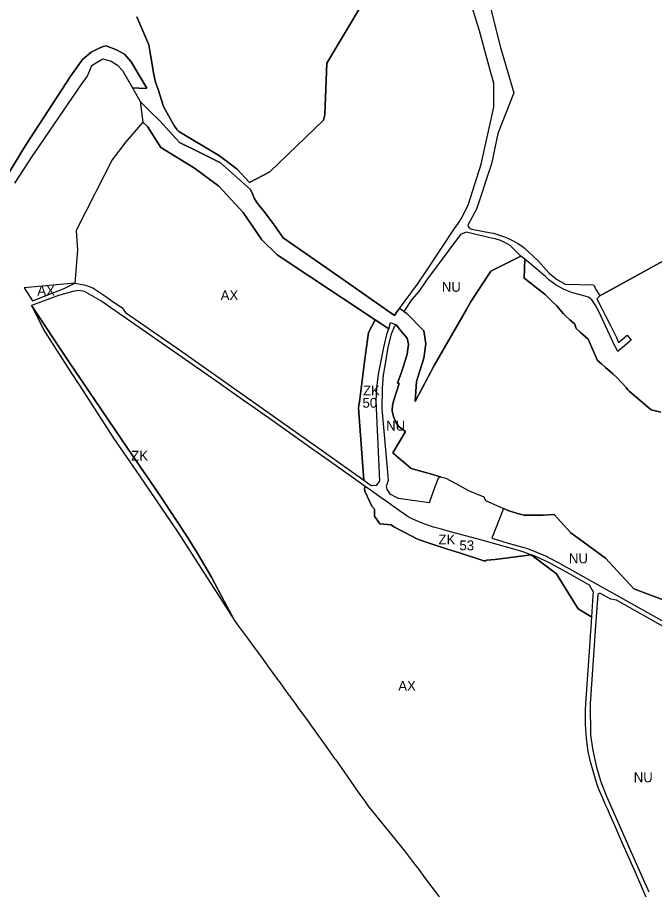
# Model space of a CAD drawing. Extents: x -521939 to -516426, y -1197857 to -1189551.
# Drawn here: x -519377 to -518730, y -1194658 to -1193772 of the extents above; entities that cross this region are included whole.
import ezdxf

# ---------------------------------------------------------------- set-up
doc = ezdxf.new("R2010")
doc.units = 0
for name, color, linetype in [('90640013', 7, 'Continuous'), ('90710013', 7, 'Continuous'), ('90710023', 7, 'Continuous'), ('90730013', 7, 'Continuous'), ('90760013', 7, 'Continuous'), ('ID_navrh', 7, 'Continuous')]:
    doc.layers.add(name, color=color, linetype=linetype)

msp = doc.modelspace()

# ---------------------------------------------------------------- linework, layer by layer
at = {"layer": '90640013'}
for points in [[(-519260.59, -1193843.56), (-519254.04, -1193843.81), (-519247.48, -1193844.06), (-519246.03, -1193843.78), (-519261.79, -1193816.98), (-519268.67, -1193809.37), (-519276.88, -1193804.99), (-519287.39, -1193800.73), (-519290.34, -1193801.33), (-519294.27, -1193803.26), (-519302.54, -1193807.3), (-519311.2, -1193814.52), (-519323.09, -1193831.25), (-519369.32, -1193902.04), (-519392.44, -1193939.94)], [(-519380, -1193940.17), (-519361.83, -1193912.1), (-519359.6, -1193908.65), (-519312.51, -1193840.49), (-519306.7, -1193831.79), (-519305.86, -1193830.53), (-519301.72, -1193820.72), (-519297.22, -1193817.84), (-519290.56, -1193813.88), (-519282.04, -1193816.28), (-519275.8, -1193820.56), (-519270.58, -1193825.99), (-519260.59, -1193843.56)], [(-518723.34, -1194172.97), (-518733.26, -1194170.62), (-518755.73, -1194151.42), (-518756.87, -1194150.17), (-518758.5, -1194148.35), (-518768.19, -1194137.67), (-518772.3, -1194134.01), (-518779.55, -1194127.56), (-518783.83, -1194123.78), (-518787.71, -1194120.29), (-518790.2, -1194114.91), (-518797.22, -1194098.85), (-518805.32, -1194091.65), (-518809.4, -1194088.06), (-518810.87, -1194083.64), (-518815.94, -1194078.99), (-518820.23, -1194075.04), (-518822.48, -1194072.97), (-518827.78, -1194066.65), (-518829.19, -1194065.02), (-518833.88, -1194060.52), (-518841.13, -1194053.49), (-518842.7, -1194051.99), (-518848.33, -1194047.58), (-518856.71, -1194041.04), (-518862.24, -1194036.73), (-518861.8, -1194017.37), (-518865.76, -1194014.41), (-518896.14, -1194029.57), (-518916.93, -1194061.2), (-518921.14, -1194068.53), (-518953.95, -1194125.44), (-518973.19, -1194162.2), (-518971.79, -1194141.85), (-518968.52, -1194131.03), (-518964.36, -1194117.94), (-518962.32, -1194103.53), (-518964.52, -1194090.45), (-518981.72, -1194072.81), (-518984.64, -1194070.77), (-518989.19, -1194067.6), (-518991.71, -1194071.11), (-518994.22, -1194074.61), (-519050.8, -1194035.17), (-519107.38, -1193995.73), (-519116.99, -1193982.41), (-519126.59, -1193969.09), (-519130.42, -1193964.54), (-519134.25, -1193959.98), (-519136.7, -1193955.42), (-519138.63, -1193951.03), (-519140.56, -1193946.64), (-519155.83, -1193933.12), (-519171.1, -1193919.6), (-519191.98, -1193909.24), (-519212.86, -1193898.88), (-519222.82, -1193887.86), (-519232.78, -1193876.84), (-519242.8, -1193867.04), (-519252.82, -1193857.23), (-519249.93, -1193878.39), (-519245.14, -1193882.61), (-519231.57, -1193904.08), (-519197.38, -1193925.03), (-519172.57, -1193943.22), (-519147.85, -1193970.15), (-519129.07, -1193997.96), (-519113.44, -1194013.16), (-519013.71, -1194079.07), (-518999.95, -1194088.17), (-518998.31, -1194081.79), (-518992.34, -1194084.24)], [(-518992.34, -1194084.24), (-518987.46, -1194090.71), (-518981.15, -1194097.64), (-518979.93, -1194103.79), (-518981.36, -1194113.88), (-518985.48, -1194127.27), (-518987.54, -1194133.31), (-518990.75, -1194142.5), (-518991.04, -1194143.46), (-518989.57, -1194143.91), (-518994.89, -1194160.62), (-518996.22, -1194165.66), (-518996.46, -1194171.39), (-518995.35, -1194177.39), (-518992.7, -1194183.09), (-518989.97, -1194187.05), (-518987.24, -1194189.51), (-518983, -1194192.63), (-518995.91, -1194214.24), (-518988.08, -1194220.82), (-518984.22, -1194224), (-518977.21, -1194230.09), (-518968.6, -1194232.51), (-518962.5, -1194234.23), (-518957.42, -1194235.65), (-518947.28, -1194238.51), (-518942.14, -1194239.95), (-518937.68, -1194242.28), (-518931.93, -1194245.39), (-518922.65, -1194250.42), (-518918.24, -1194252.79), (-518916.45, -1194253.54), (-518912.68, -1194255.11), (-518903.43, -1194258.95), (-518901.77, -1194262.69), (-518884.06, -1194270.49), (-518883.22, -1194270.86), (-518877.97, -1194273.16), (-518871.17, -1194275.18), (-518869.07, -1194275.8), (-518867.56, -1194276.25), (-518862.81, -1194277.65), (-518855.61, -1194277.58), (-518843.09, -1194277.49), (-518831.78, -1194276.92), (-518814.85, -1194295.64), (-518779.83, -1194321.26), (-518750.93, -1194352.24), (-518718.32, -1194364.43)]]:
    msp.add_lwpolyline(points, dxfattribs=at)
at = {"layer": '90710013'}
msp.add_lwpolyline([(-519157.23, -1194383.9), (-519165.07, -1194369.2), (-519169.9, -1194359.97), (-519173.46, -1194353.25), (-519180.17, -1194340.54), (-519194.88, -1194315.71), (-519205.17, -1194298.93), (-519230.46, -1194260.8), (-519243.94, -1194240.87), (-519248.58, -1194234.02), (-519265.68, -1194209.52), (-519325.55, -1194120.93), (-519363.03, -1194064.67), (-519362.31, -1194066.11), (-519350.72, -1194089.46), (-519329.11, -1194123.6), (-519317.88, -1194140.81), (-519314.59, -1194145.01), (-519279.95, -1194199.35), (-519253.43, -1194237.74), (-519214.57, -1194294.83), (-519157.23, -1194383.9)], dxfattribs=at)
at = {"layer": '90710023'}
for points in [[(-519025.2, -1194242.02), (-519017.78, -1194247.27), (-519012.22, -1194247.18), (-519009.11, -1194242.54), (-519012.79, -1194161.44), (-519012.2, -1194148.13), (-519010.43, -1194134.4), (-519004.84, -1194105.44), (-519001.62, -1194092.79), (-518999.95, -1194088.17), (-519013.71, -1194079.07), (-519020.73, -1194091.88), (-519024.61, -1194121.8), (-519028.49, -1194151.72), (-519029.89, -1194162.52), (-519030.29, -1194165.62), (-519030.69, -1194168.71), (-519027.95, -1194205.37), (-519025.2, -1194242.02)], [(-518793.68, -1194380.64), (-518792.24, -1194359.26), (-518791.99, -1194355.76), (-518795.83, -1194348.62), (-518799.64, -1194346.49), (-518816.36, -1194337.16), (-518838.06, -1194325.4), (-518851.56, -1194319.21), (-518862.69, -1194315.05), (-518865.77, -1194314.1), (-518872.91, -1194311.92), (-518892.05, -1194306.64), (-518905.25, -1194303.03), (-518910.54, -1194301.58), (-518937.1, -1194294.31), (-518946.44, -1194291.75), (-518954.36, -1194289.64), (-518962.17, -1194287.03), (-518966.08, -1194285.71), (-518975.52, -1194281.45), (-518980.26, -1194279.31), (-518993.95, -1194269.72), (-519001.41, -1194264.41), (-519008.87, -1194259.09), (-519017.53, -1194252.96), (-519023.94, -1194248.41), (-519024.71, -1194250.04), (-519024.49, -1194253.08), (-519017.06, -1194268.42), (-519014.59, -1194271.5), (-519014.52, -1194278.4), (-519009.2, -1194286.28), (-518997.55, -1194287.28), (-518994.7, -1194289.4), (-518975.86, -1194299.17), (-518972.84, -1194300.73), (-518969.65, -1194302.39), (-518959.1, -1194305.82), (-518939.19, -1194312.3), (-518928.2, -1194315.87), (-518903.28, -1194323.98), (-518901.43, -1194323.75), (-518900.67, -1194323.31), (-518891.75, -1194322.51), (-518855.36, -1194317.86), (-518829.53, -1194336.97), (-518816.88, -1194357.57), (-518807.62, -1194372.64), (-518794.51, -1194380.48), (-518793.68, -1194380.64)]]:
    msp.add_lwpolyline(points, dxfattribs=at)
at = {"layer": '90730013'}
for points in [[(-519392.44, -1193939.94), (-519369.32, -1193902.04), (-519323.09, -1193831.25), (-519311.2, -1193814.52), (-519302.54, -1193807.3), (-519294.27, -1193803.26), (-519290.34, -1193801.33), (-519287.39, -1193800.73), (-519276.88, -1193804.99), (-519268.67, -1193809.37), (-519261.79, -1193816.98), (-519246.03, -1193843.78), (-519247.48, -1193844.06), (-519254.04, -1193843.81), (-519260.59, -1193843.56), (-519252.82, -1193857.23), (-519242.8, -1193867.04), (-519232.78, -1193876.84), (-519222.82, -1193887.86), (-519212.86, -1193898.88), (-519191.98, -1193909.24), (-519171.1, -1193919.6), (-519155.83, -1193933.12), (-519140.56, -1193946.64), (-519138.63, -1193951.03), (-519136.7, -1193955.42), (-519134.25, -1193959.98), (-519130.42, -1193964.54), (-519126.59, -1193969.09), (-519116.99, -1193982.41), (-519107.38, -1193995.73), (-519050.8, -1194035.17), (-518994.22, -1194074.61), (-518991.71, -1194071.11), (-518989.19, -1194067.6), (-518970.85, -1194043.01), (-518961.6, -1194029.39), (-518933.03, -1193986.3), (-518929.34, -1193981.24), (-518926.25, -1193976.62), (-518919.27, -1193962.65), (-518906.17, -1193921.14), (-518893.26, -1193863.08), (-518893.29, -1193838.77), (-518896.5, -1193826.92), (-518907.68, -1193785.6), (-518926.27, -1193725.26)], [(-518905.57, -1193725.38), (-518886.46, -1193802.5), (-518872.98, -1193848.37), (-518889.3, -1193889.95), (-518895.73, -1193920.57), (-518910.79, -1193966.72), (-518919.72, -1193983.02), (-518919.42, -1193984.21), (-518917.8, -1193986.11), (-518915.51, -1193987.1), (-518896.17, -1193990.58), (-518893.56, -1193991.17), (-518888.41, -1193992.64), (-518883.37, -1193994.4), (-518878.43, -1193996.47), (-518873.62, -1193998.81), (-518868.96, -1194001.44), (-518864.46, -1194004.33), (-518862.25, -1194005.95), (-518847.72, -1194019.68), (-518837.23, -1194031.38), (-518829.44, -1194037.71), (-518820.8, -1194042.81), (-518791.79, -1194043.69), (-518788.68, -1194049.26), (-518785.58, -1194054.84), (-518720.61, -1194019.07)], [(-519025.65, -1193756.19), (-519062.93, -1193818.34), (-519065.01, -1193870.53), (-519066.27, -1193876.16), (-519120.74, -1193928.89), (-519141.58, -1193939.77), (-519154.26, -1193925.95), (-519171.95, -1193912.59), (-519213.53, -1193887.89), (-519215.12, -1193886.12), (-519217.8, -1193882.51), (-519221.81, -1193875.3), (-519228.9, -1193862.43), (-519234.57, -1193845.15), (-519237, -1193837.71), (-519238.75, -1193829.99), (-519241.81, -1193812.07), (-519244.01, -1193799.73), (-519255.98, -1193771.28)], [(-518984.64, -1194070.77), (-518981.72, -1194072.81), (-518964.52, -1194090.45), (-518962.32, -1194103.53), (-518964.36, -1194117.94), (-518968.52, -1194131.03), (-518971.79, -1194141.85), (-518973.19, -1194162.2), (-518953.95, -1194125.44), (-518921.14, -1194068.53), (-518916.93, -1194061.2), (-518896.14, -1194029.57), (-518865.76, -1194014.41), (-518876.72, -1194003.63), (-518881.5, -1194000.92), (-518886.53, -1193998.68), (-518891.75, -1193996.93), (-518897.11, -1193995.69), (-518901.17, -1193994.65), (-518921.36, -1193990.1), (-518927.19, -1193992.35), (-518961.57, -1194038.67), (-518969.27, -1194050.28), (-518976.81, -1194058.82), (-518984.64, -1194070.77)], [(-518720.61, -1194019.07), (-518785.58, -1194054.84), (-518788.48, -1194057.64), (-518784.06, -1194066.31), (-518779.64, -1194074.99), (-518774.55, -1194084.96), (-518769.47, -1194094.94), (-518768.35, -1194097.15), (-518768.35, -1194097.16), (-518767.38, -1194099.7), (-518766.41, -1194102.26), (-518757.64, -1194094.78), (-518753.59, -1194099.63), (-518762.33, -1194107.13), (-518767.02, -1194111.44), (-518770.01, -1194106.27), (-518770.34, -1194105.7), (-518773.38, -1194099.24), (-518775.15, -1194094.55), (-518779.68, -1194085.15), (-518784.2, -1194075.75), (-518788.94, -1194065.87), (-518793.56, -1194058.95), (-518797.05, -1194056.07), (-518804.1, -1194053.89), (-518813.11, -1194051.65), (-518821.77, -1194048.27), (-518829.92, -1194043.82), (-518837.43, -1194038.35), (-518840.81, -1194035.16), (-518861.8, -1194017.37), (-518862.24, -1194036.73), (-518856.71, -1194041.04), (-518848.33, -1194047.58), (-518842.7, -1194051.99), (-518841.13, -1194053.49), (-518833.88, -1194060.52), (-518829.19, -1194065.02), (-518827.78, -1194066.65), (-518822.48, -1194072.97), (-518820.23, -1194075.04), (-518815.94, -1194078.99), (-518810.87, -1194083.64), (-518809.4, -1194088.06), (-518805.32, -1194091.65), (-518797.22, -1194098.85), (-518790.2, -1194114.91), (-518787.71, -1194120.29), (-518783.83, -1194123.78), (-518779.55, -1194127.56), (-518772.3, -1194134.01), (-518768.19, -1194137.67), (-518758.5, -1194148.35), (-518756.87, -1194150.17), (-518755.73, -1194151.42), (-518733.26, -1194170.62), (-518723.34, -1194172.97)], [(-518992.34, -1194084.24), (-518994.52, -1194086.35), (-518997.57, -1194093.58), (-519000.87, -1194106.75), (-519004.5, -1194128.01), (-519005.71, -1194135.09), (-519006.82, -1194148.88), (-519007.1, -1194169.38), (-519001.58, -1194230.24), (-519000.5, -1194242.27), (-519002.57, -1194248.44), (-519001.67, -1194251.84), (-518998.9, -1194255.97), (-518992.56, -1194259.17), (-518990.61, -1194260.15), (-518958.46, -1194264.63), (-518953.02, -1194249.57), (-518950.81, -1194243.44), (-518949.41, -1194239.58), (-518947.28, -1194238.51), (-518957.42, -1194235.65), (-518962.5, -1194234.23), (-518968.6, -1194232.51), (-518977.21, -1194230.09), (-518984.22, -1194224), (-518988.08, -1194220.82), (-518995.91, -1194214.24), (-518983, -1194192.63), (-518987.24, -1194189.51), (-518989.97, -1194187.05), (-518992.7, -1194183.09), (-518995.35, -1194177.39), (-518996.46, -1194171.39), (-518996.22, -1194165.66), (-518994.89, -1194160.62), (-518989.57, -1194143.91), (-518991.04, -1194143.46), (-518990.75, -1194142.5), (-518987.54, -1194133.31), (-518985.48, -1194127.27), (-518981.36, -1194113.88), (-518979.93, -1194103.79), (-518981.15, -1194097.64), (-518987.46, -1194090.71), (-518992.34, -1194084.24)], [(-518718.32, -1194364.43), (-518750.93, -1194352.24), (-518779.83, -1194321.26), (-518814.85, -1194295.64), (-518831.78, -1194276.92), (-518843.09, -1194277.49), (-518855.61, -1194277.58), (-518862.81, -1194277.65), (-518867.56, -1194276.25), (-518869.07, -1194275.8), (-518871.17, -1194275.18), (-518877.97, -1194273.16), (-518883.22, -1194270.86), (-518895.2, -1194301.05), (-518885.16, -1194303.95), (-518883.44, -1194304.45), (-518858.91, -1194311.54), (-518840.84, -1194318.92), (-518827.82, -1194325.64), (-518716.88, -1194387.49)], [(-518670.02, -1194641.47), (-518673.12, -1194633.99), (-518677.75, -1194626.77), (-518684.82, -1194603.84), (-518691.92, -1194568.93), (-518697.48, -1194547.94), (-518710.33, -1194509.64), (-518719.92, -1194464.77), (-518719.42, -1194447.81), (-518713.15, -1194395.12), (-518768.4, -1194363.91), (-518774.24, -1194362.95), (-518785.49, -1194356.68), (-518787.62, -1194357.85), (-518789.82, -1194390.1), (-518795.17, -1194469.16), (-518794.77, -1194500.94), (-518792.66, -1194516.7), (-518789.28, -1194532.25), (-518784.67, -1194547.47), (-518778.85, -1194562.27), (-518749.75, -1194628.33), (-518735.68, -1194660.28)]]:
    msp.add_lwpolyline(points, dxfattribs=at)
at = {"layer": '90760013'}
for points in [[(-519255.98, -1193771.28), (-519244.01, -1193799.73), (-519241.81, -1193812.07), (-519238.75, -1193829.99), (-519237, -1193837.71), (-519234.57, -1193845.15), (-519228.9, -1193862.43), (-519221.81, -1193875.3), (-519217.8, -1193882.51), (-519215.12, -1193886.12), (-519213.53, -1193887.89), (-519171.95, -1193912.59), (-519154.26, -1193925.95), (-519141.58, -1193939.77), (-519120.74, -1193928.89), (-519066.27, -1193876.16), (-519065.01, -1193870.53), (-519062.93, -1193818.34), (-519025.65, -1193756.19)], [(-519025.2, -1194242.02), (-519027.95, -1194205.37), (-519030.69, -1194168.71), (-519030.29, -1194165.62), (-519029.89, -1194162.52), (-519028.49, -1194151.72), (-519024.61, -1194121.8), (-519020.73, -1194091.88), (-519013.71, -1194079.07), (-519113.44, -1194013.16), (-519129.07, -1193997.96), (-519147.85, -1193970.15), (-519172.57, -1193943.22), (-519197.38, -1193925.03), (-519231.57, -1193904.08), (-519245.14, -1193882.61), (-519249.93, -1193878.39), (-519267.42, -1193898.35), (-519281.11, -1193916.6), (-519296.93, -1193947.58), (-519298.75, -1193951.14), (-519317.82, -1193988.47), (-519316.4, -1194008.43), (-519319.06, -1194042.03), (-519308.16, -1194044.03), (-519300.97, -1194046.69), (-519287.59, -1194055.46), (-519282.43, -1194059.02), (-519271.05, -1194066.85), (-519267.59, -1194071.65), (-519211.54, -1194110.23), (-519066.22, -1194213.01), (-519025.2, -1194242.02)], [(-519370.51, -1194046.68), (-519362.08, -1194059.92), (-519330.1, -1194047.22), (-519319.06, -1194042.03), (-519370.51, -1194046.68)], [(-518736.23, -1194670.16), (-518749.32, -1194640.47), (-518754.77, -1194628.15), (-518760.69, -1194614.68), (-518764.33, -1194606.4), (-518770.31, -1194592.82), (-518775.18, -1194581.75), (-518777.47, -1194576.55), (-518779.91, -1194571.02), (-518782.8, -1194564.37), (-518785.78, -1194557.7), (-518788.05, -1194551.39), (-518794.95, -1194528.17), (-518797.21, -1194517.5), (-518799.05, -1194504.36), (-518800.02, -1194490.26), (-518800.14, -1194475.82), (-518799.63, -1194468.85), (-518795.42, -1194406.33), (-518794.97, -1194399.7), (-518794.42, -1194391.59), (-518793.68, -1194380.64), (-518794.51, -1194380.48), (-518807.62, -1194372.64), (-518816.88, -1194357.57), (-518829.53, -1194336.97), (-518855.36, -1194317.86), (-518891.75, -1194322.51), (-518900.67, -1194323.31), (-518901.43, -1194323.75), (-518903.28, -1194323.98), (-518928.2, -1194315.87), (-518939.19, -1194312.3), (-518959.1, -1194305.82), (-518969.65, -1194302.39), (-518972.84, -1194300.73), (-518975.86, -1194299.17), (-518994.7, -1194289.4), (-518997.55, -1194287.28), (-519009.2, -1194286.28), (-519014.52, -1194278.4), (-519014.59, -1194271.5), (-519017.06, -1194268.42), (-519024.49, -1194253.08), (-519024.71, -1194250.04), (-519023.94, -1194248.41), (-519035.71, -1194240.08), (-519061.74, -1194221.72), (-519078.64, -1194209.72), (-519117.67, -1194182.15), (-519139.27, -1194166.84), (-519146.5, -1194161.75), (-519172.35, -1194143.44), (-519292.85, -1194059.74), (-519309.32, -1194050.2), (-519315.34, -1194049.18), (-519321.14, -1194050.16), (-519335.55, -1194054.45), (-519363.03, -1194064.67), (-519325.55, -1194120.93), (-519265.68, -1194209.52), (-519248.58, -1194234.02), (-519243.94, -1194240.87), (-519230.46, -1194260.8), (-519205.17, -1194298.93), (-519194.88, -1194315.71), (-519180.17, -1194340.54), (-519173.46, -1194353.25), (-519169.9, -1194359.97), (-519165.07, -1194369.2), (-519157.23, -1194383.9), (-519156.68, -1194384.65), (-519153.63, -1194388.82), (-519144.72, -1194401.02), (-519137.6, -1194410.77), (-519133.58, -1194416.25), (-519129.86, -1194421.36), (-519125.45, -1194427.38), (-519122.13, -1194431.93), (-519112.97, -1194444.52), (-519110.47, -1194447.96), (-519104.26, -1194456.48), (-519095.22, -1194468.91), (-519091.7, -1194473.75), (-519091.59, -1194473.9), (-519084.4, -1194483.87), (-519076.87, -1194494.31), (-519064.02, -1194512.12), (-519055.04, -1194524.57), (-519053.95, -1194526.13), (-519045.48, -1194538.19), (-519031.02, -1194558.79), (-519027.36, -1194564.02), (-519024.43, -1194568.18), (-519020.97, -1194573.11), (-518983.98, -1194618.4), (-518975.82, -1194629.24), (-518968.52, -1194638.95), (-518964.64, -1194644.1), (-518948.85, -1194665.08)]]:
    msp.add_lwpolyline(points, dxfattribs=at)

# ---------------------------------------------------------------- texts
at = {"layer": '90710013'}
msp.add_text('ZK', height=10, rotation=360, dxfattribs=at).set_placement((-519261.83, -1194222.11))
at = {"layer": '90710023'}
for p in [(-519026.17, -1194155.96), (-518949.44, -1194307.19)]:
    msp.add_text('ZK', height=10, rotation=0, dxfattribs=at).set_placement(p)
at = {"layer": '90730013'}
for rotation, p in [(0, (-518946.06, -1194050.59)), (0, (-519002.7, -1194191.63)), (0, (-518816.81, -1194326.43)), (360, (-518750.97, -1194548.83))]:
    msp.add_text('NU', height=10, rotation=rotation, dxfattribs=at).set_placement(p)
at = {"layer": '90760013'}
for p in [(-519357.25, -1194054.44), (-519170.86, -1194059.07), (-518990.3, -1194455.9)]:
    msp.add_text('AX', height=10, rotation=360, dxfattribs=at).set_placement(p)
at = {"layer": 'ID_navrh'}
for s, p in [('50', (-519026.74, -1194168.38)), ('53', (-518928.12, -1194313.23))]:
    msp.add_text(s, height=10, rotation=0, dxfattribs=at).set_placement(p)

doc.saveas('drawing.dxf')
